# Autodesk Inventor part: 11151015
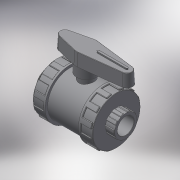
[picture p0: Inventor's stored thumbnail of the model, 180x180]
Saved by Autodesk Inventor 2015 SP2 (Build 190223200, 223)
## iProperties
Created: 2017-11
Part Number: 11151015
Material: Generic
Description: 2/NUT VALVE FEMALE THREAD 1 1/2" PVC
Document SubType Name: Modeling
Designer: KIM
Density: 1 g/cm^3
Appearance: Default
Author: KIM
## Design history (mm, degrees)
derived "111510.ipt"
feature "Solid1::111510.ipt"
tag "TaggingFeature1"
body "Solid1"
other parameters: "d0" = 142, "d1" = 44.845, "d2" = 96, "d3" = 22, "d4" = 35.876, "d5" = 15.4, "d7" = 62.783, "d8" = 86.4, "d13" = 1.34535, "d23" = 22, "d24" = 92.16, "d25" = 0.8969, "d26" = 1.34535, "d27" = 14.4, "d28" = 7.2, "d29" = 16.5, "d30" = 0, "d35" = 1.34535, "d39" = 48, "d45" = 360 deg, "d47" = 0.8969, "d50" = 52.8, "d51" = 28.8, "d53" = 0, "d55" = 8.969, "d56" = 4.4845, "d57" = 15.4, "d58" = 0, "d59" = 1.34535, "d61" = 360 deg, "d63" = 38.4, "d64" = 86, "d68" = 19.2, "d69" = 33, "d70" = 21.5, "d71" = 3 deg, "d73" = 1.92, "d74" = 44, "d75" = 2.58, "d76" = 0, "d77" = 0.8969, "G_" = 44.845, "l_" = 22, "H_" = 142, "K_" = 96, "F_" = 86, "d67" = 38.4, "d72" = 9.6
